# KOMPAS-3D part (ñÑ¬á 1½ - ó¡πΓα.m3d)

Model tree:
1. Эскиз:1
2. Операция выдавливания:1
     Расстояние 1 = 0.6
3. Эскиз:2
4. Вырезать элемент выдавливания:1
     Толщина стенки 1 = 3; Толщина стенки 2 = 3; Расстояние 1 = 10
5. Эскиз:3
6. Вырезать элемент выдавливания:2
     Толщина стенки 1 = 3; Толщина стенки 2 = 3; Расстояние 1 = 10
7. Эскиз:4
8. Вырезать элемент выдавливания:3
     Толщина стенки 1 = 3; Толщина стенки 2 = 3; Расстояние 1 = 10
9. Эскиз:5
10. Вырезать элемент выдавливания:4
     Толщина стенки 1 = 3; Толщина стенки 2 = 3; Расстояние 1 = 10
11. Эскиз:6
12. Вырезать элемент выдавливания:5
     Расстояние 1 = 10
